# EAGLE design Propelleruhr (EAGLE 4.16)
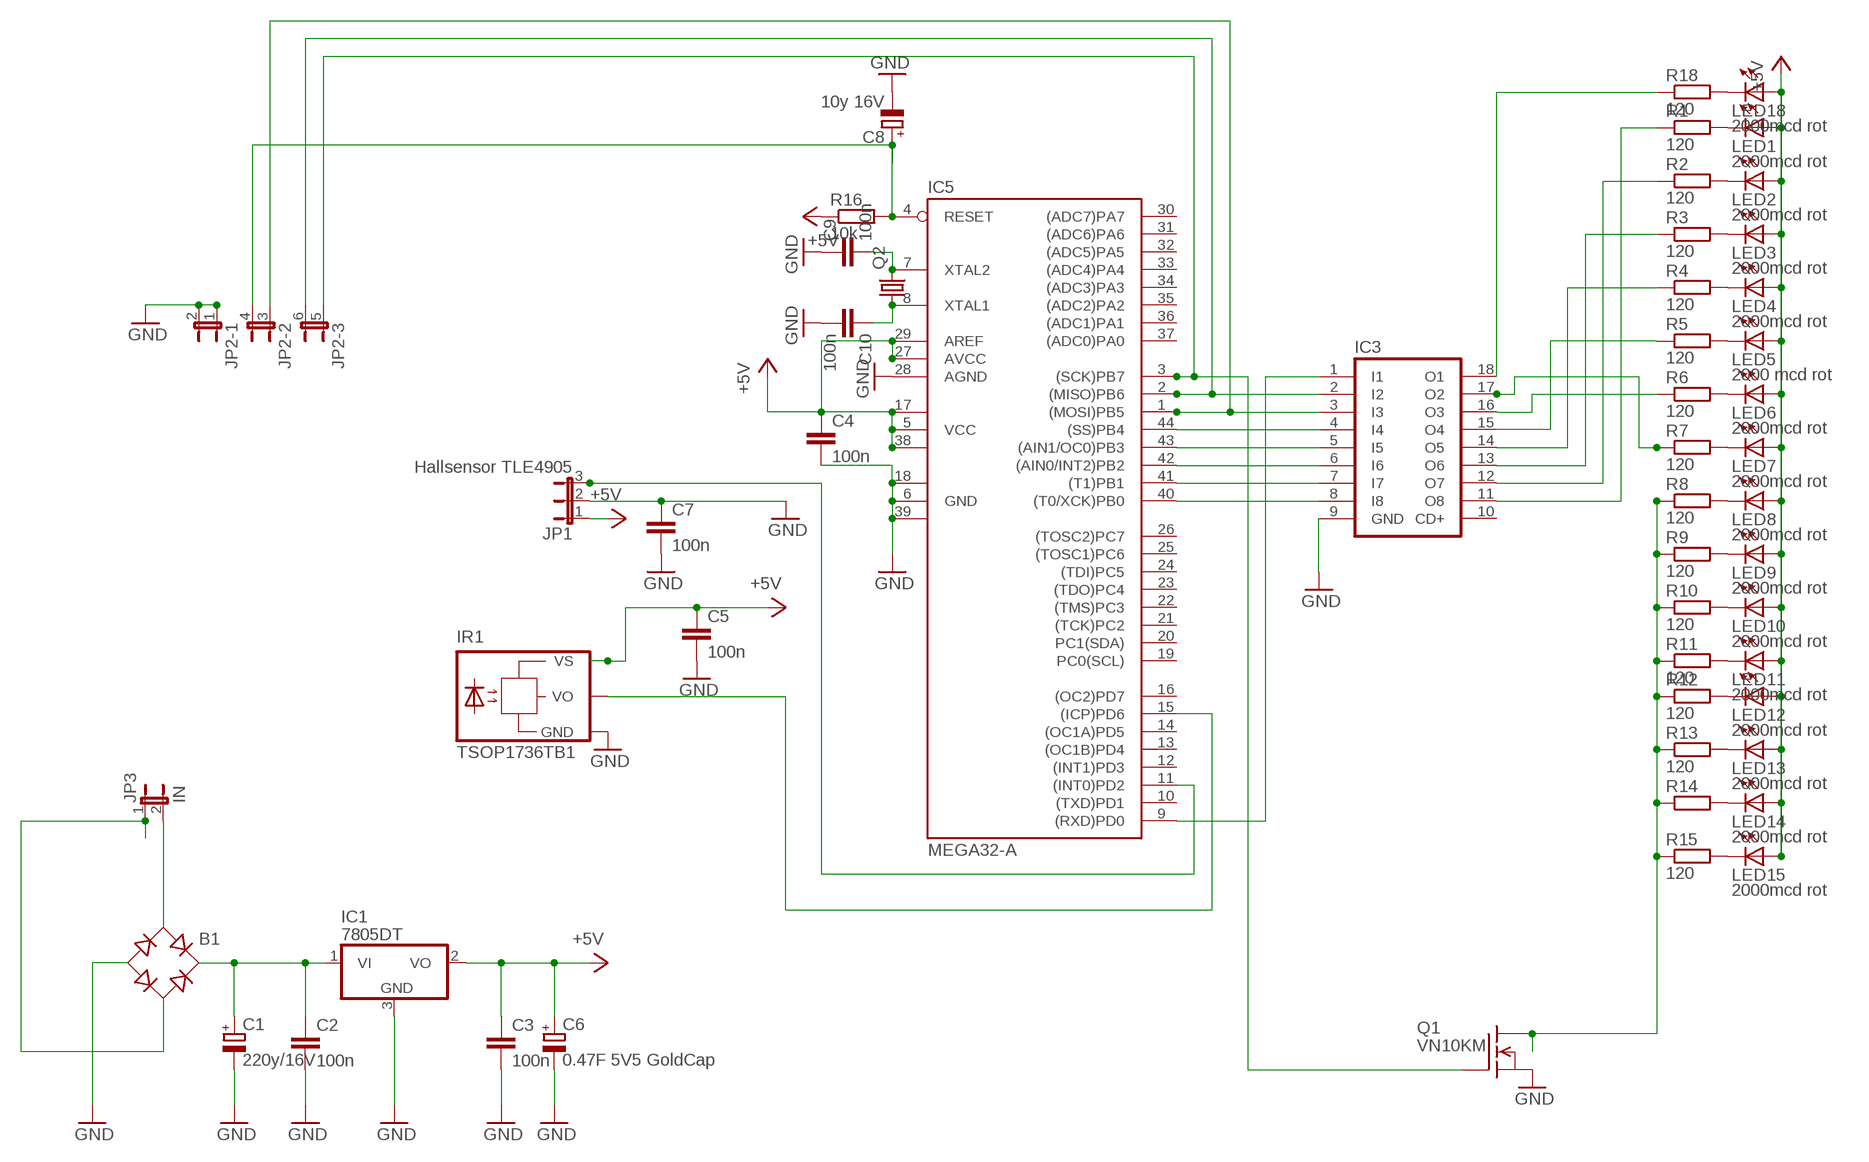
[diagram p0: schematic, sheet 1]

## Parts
B1  RB1A  [RB1A]
C1  220y/16V  CPOL-EU140CLH-0810  [140CLH-0810]
C2  100n  C-EUC1812  [C1812]
C3  100n  C-EUC1812  [C1812]
C4  100n  C-EUC1812  [C1812]
C5  100n  C-EUC1812  [C1812]
C6  0.47F 5V5 GoldCap  CPOL-EU140CLH-0810  [140CLH-0810]
C7  100n  C-EUC1812  [C1812]
C8  10y 16V  CPOL-EU140CLH-0810  [140CLH-0810]
C9  100n  C-EUC1812  [C1812]
C10  100n  C-EUC1812  [C1812]
IC1  7805DT  [TO252]
IC3  ULN2803A  [DIL18]
IC5  MEGA32-A  [TQFP44]
IR1  TSOP1736TB1  [TSOP17_TB1]
JP1  Hallsensor TLE4905  JP2W  [JP2W]
JP2  JP3QE  [JP3Q]
JP3  IN  JP1E  [JP1]
LED1  2000mcd rot  LED3MM  [LED3MM]
LED2  2000mcd rot  LED3MM  [LED3MM]
LED3  2000mcd rot  LED3MM  [LED3MM]
LED4  2000mcd rot  LED3MM  [LED3MM]
LED5  2000 mcd rot  LED3MM  [LED3MM]
LED6  2000mcd rot  LED3MM  [LED3MM]
LED7  2000mcd rot  LED3MM  [LED3MM]
LED8  2000mcd rot  LED3MM  [LED3MM]
LED9  2000mcd rot  LED3MM  [LED3MM]
LED10  2000mcd rot  LED3MM  [LED3MM]
LED11  2000mcd rot  LED3MM  [LED3MM]
LED12  2000mcd rot  LED3MM  [LED3MM]
LED13  2000mcd rot  LED3MM  [LED3MM]
LED14  2000mcd rot  LED3MM  [LED3MM]
LED15  2000mcd rot  LED3MM  [LED3MM]
LED18  2000mcd rot  LED3MM  [LED3MM]
Q1  VN10KM  [TO237]
Q2  CRYSTALHC18U-V  [HC18U-V]
R1  120  R-EU_M0805  [M0805]
R2  120  R-EU_M0805  [M0805]
R3  120  R-EU_M0805  [M0805]
R4  120  R-EU_M0805  [M0805]
R5  120  R-EU_M0805  [M0805]
R6  120  R-EU_M0805  [M0805]
R7  120  R-EU_M0805  [M0805]
R8  120  R-EU_M0805  [M0805]
R9  120  R-EU_M0805  [M0805]
R10  120  R-EU_M0805  [M0805]
R11  120  R-EU_M0805  [M0805]
R12  120  R-EU_M0805  [M0805]
R13  120  R-EU_M0805  [M0805]
R14  R-EU_M0805  [M0805]
R15  120  R-EU_M0805  [M0805]
R16  10k  R-R0805  [R0805]
R18  120  R-EU_M0805  [M0805]

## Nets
+5V: C3.1 C4.1 C5.1 C6.+ IC1.2(VO) IC5.5(VCC) IC5.17(VCC1) IC5.27(AVCC) IC5.29(AREF) IC5.38(VCC2) IR1.VS JP1.1 LED1.A LED2.A LED3.A LED4.A LED5.A LED6.A LED7.A LED8.A LED9.A LED10.A LED11.A LED12.A LED13.A LED14.A LED15.A LED18.A R16.1
GND: B1.- C1.- C2.2 C3.2 C4.2 C5.2 C6.- C7.1 C7.2 C8.- C9.1 C10.2 IC1.3(GND) IC3.9(GND) IC5.6(GND) IC5.18(GND1) IC5.28(AGND) IC5.39(GND2) IR1.GND JP1.2 JP2.1 JP2.2 Q1.3(S)
N$1: C8.+ IC5.4(RESET) JP2.4 R16.2
N$2: IC3.8(I8) IC5.40((T0/XCK)PB0)
N$3: IC3.7(I7) IC5.41((T1)PB1)
N$4: IC3.6(I6) IC5.42((AIN0/INT2)PB2)
N$5: IC3.5(I5) IC5.43((AIN1/OC0)PB3)
N$6: IC3.4(I4) IC5.44((SS)PB4)
N$7: IC3.3(I3) IC5.1((MOSI)PB5) JP2.3
N$8: IC3.2(I2) IC5.2((MISO)PB6) JP2.6
N$9: IC3.1(I1) IC5.9((RXD)PD0)
N$10: IC5.3((SCK)PB7) JP2.5 Q1.2(G)
N$11: IC5.15((ICP)PD6) IR1.VO
N$12: IC5.11((INT0)PD2) JP1.3
N$13: LED1.K(C) R1.2
N$14: LED2.K(C) R2.2
N$15: LED3.K(C) R3.2
N$16: LED4.K(C) R4.2
N$17: LED5.K(C) R5.2
N$18: LED6.K(C) R6.2
N$19: LED7.K(C) R7.2
N$20: LED8.K(C) R8.2
N$21: LED9.K(C) R9.2
N$22: LED10.K(C) R10.2
N$23: LED11.K(C) R11.2
N$24: LED12.K(C) R12.2
N$25: LED13.K(C) R13.2
N$26: LED14.K(C) R14.2
N$27: LED15.K(C) R15.2
N$28: C9.2 IC5.7(XTAL2) Q2.2
N$29: C10.1 IC5.8(XTAL1) Q2.1
N$30: LED18.K(C) R18.2
N$31: Q1.1(D) R8.1 R9.1 R10.1 R11.1 R12.1 R13.1 R14.1 R15.1
N$32: IC3.16(O3) R6.1
N$33: IC3.11(O8) R1.1
N$34: IC3.17(O2) R7.1
N$35: IC3.12(O7) R2.1
N$36: IC3.13(O6) R3.1
N$37: IC3.14(O5) R4.1
N$38: IC3.15(O4) R5.1
N$39: IC3.18(O1) R18.1
N$42: B1.+ C1.+ C2.1 IC1.1(VI)
N$43: B1.AC1 JP3.2
N$44: B1.AC2 JP3.1
Unconnected: IC3.10(CD+) IC5.10((TXD)PD1) IC5.12((INT1)PD3) IC5.13((OC1B)PD4) IC5.14((OC1A)PD5) IC5.16((OC2)PD7) IC5.19(PC0(SCL)) IC5.20(PC1(SDA)) IC5.21((TCK)PC2) IC5.22((TMS)PC3) IC5.23((TDO)PC4) IC5.24((TDI)PC5) IC5.25((TOSC1)PC6) IC5.26((TOSC2)PC7) IC5.30((ADC7)PA7) IC5.31((ADC6)PA6) IC5.32((ADC5)PA5) IC5.33((ADC4)PA4) IC5.34((ADC3)PA3) IC5.35((ADC2)PA2) IC5.36((ADC1)PA1) IC5.37((ADC0)PA0)

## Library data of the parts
B1 = rectifier:RB1A: RECTIFIER 1 A
C1 C6 C8 = rcl:CPOL-EU: POLARIZED CAPACITOR, European symbol
C2-C5 C7 C9 C10 = rcl:C-EU: CAPACITOR, European symbol
IC1 = linear:78*: Positive VOLTAGE REGULATOR Source: http://cache.national.com/ds/LM/LM78L05.pdf http://www.fairchildsemi.com/ds/LM/LM7805.pdf
IC3 = uln-udn:ULN2803A: DRIVER ARRAY
IC5 = atmel:MEGA32: MICROCONTROLLER 32 Kbytes FLASH 2 Kbytes SRAM 1 Kbytes EEPROM USART 8-channel 10 bit ADC Source: www.atmel.com .. doc2503.pdf
IR1 = telefunken:TSOP17*TB1: TSOP17..TB1 IR Receiver Modules for Remote Control Systems Source: http://www.vishay.com/docs/82042/82042.pdf
JP1 = jumper:JP2W: JUMPER
JP2 = jumper:JP3QE: JUMPER
JP3 = jumper:JP1E: JUMPER
LED1-LED15 LED18 = led:LED: LED
Q1 = transistor-fet:VN10KM: N-Channel Enhancement MOSFET (VMOS); 60V; 0,5A; 5,0Ohm
Q2 = crystal:CRYSTAL: CRYSTAL
R1-R15 R18 = rcl:R-EU_: RESISTOR, European symbol
R16 = quantum-sensor:R: Resistor

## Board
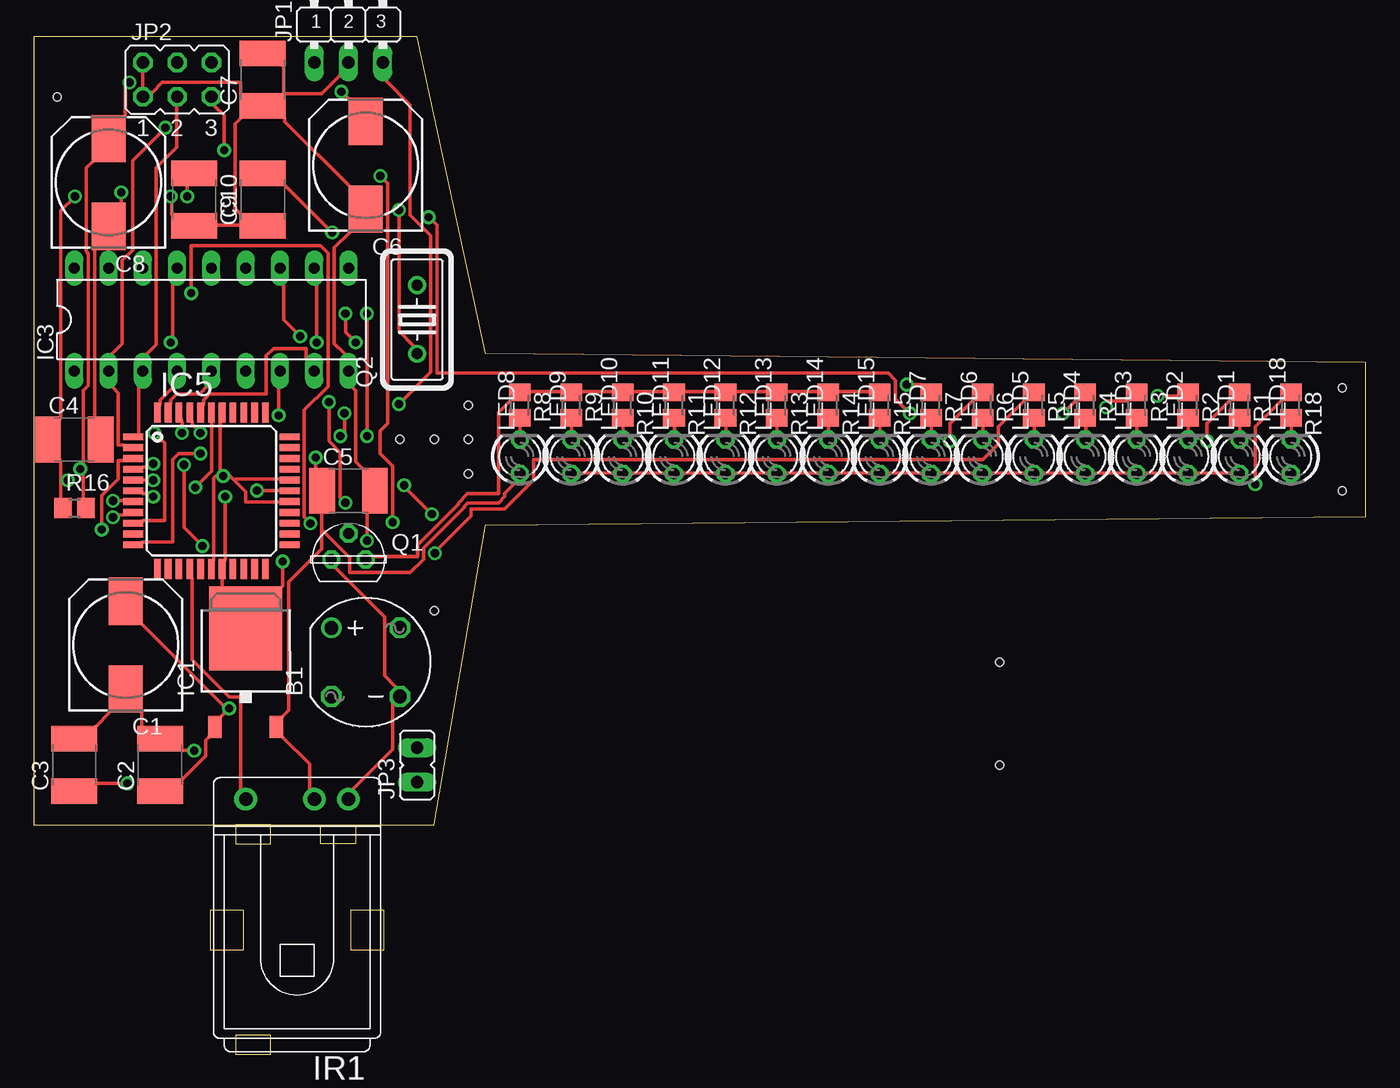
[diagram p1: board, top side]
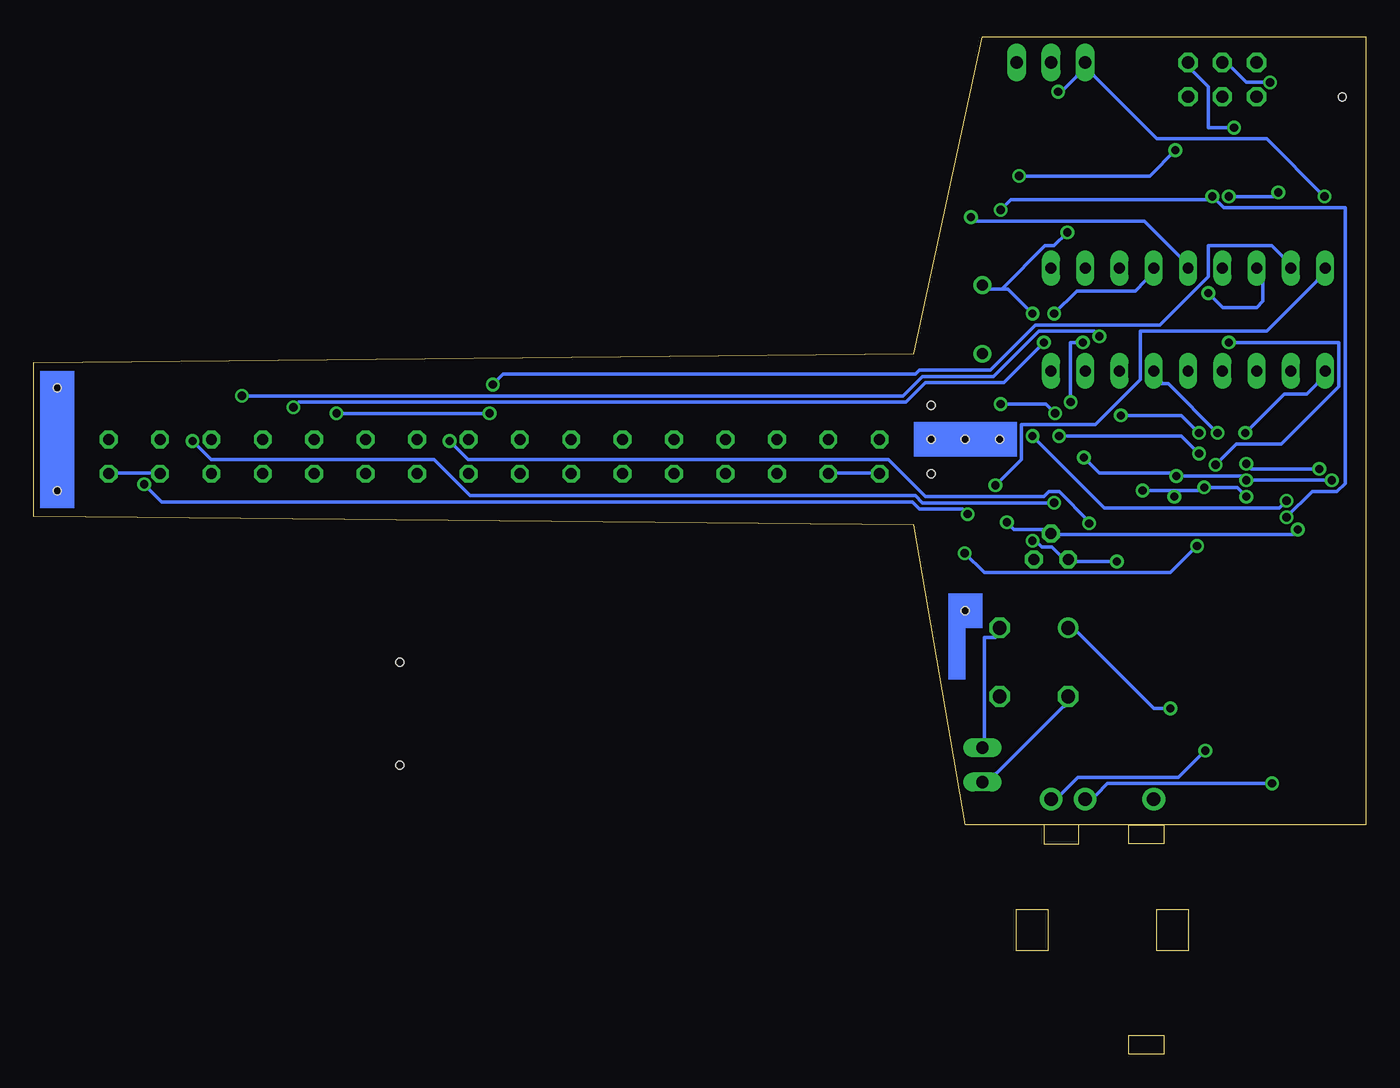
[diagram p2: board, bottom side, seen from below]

Size 98.73 x 75.41 mm. Coordinates in mm from the lower left corner, seen from the top.
Outline: 0,17 29.68,17 33.49,39.22 98.73,39.86 98.73,51.28 33.49,51.92 28.41,75.41 0,75.41 0,17
Copper layers (1*16): Top 0.035mm / dielectric 1.5mm / Bottom 0.035mm
Design rules "default": minimum track width 10mil, minimum drill 24mil, track to track 8mil, track to pad 8mil, pad to pad 8mil, via to via 8mil, smd to smd 8mil, copper to edge 40mil, drill to drill 8mil, minimum pad ring 10mil, minimum via ring 8mil, stop-mask expansion 4mil, vias tented up to drill 0mil, thermal gap 10mil
Holes 0.6 mm at 27.14,45.57 29.68,45.57 32.22,45.57 1.74,70.97 29.68,32.87 71.59,29.06 71.59,21.44 32.22,48.11 32.22,43.03 96.99,49.38 96.99,41.76

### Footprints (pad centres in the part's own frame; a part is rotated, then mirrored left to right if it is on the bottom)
RB1A = drill 1.016 round: + -2.54,2.54 | drill 1.016 octagon: - 2.54,-2.54; AC1 2.54,2.54; AC2 -2.54,-2.54
140CLH-0810 = smd 3.5 x 2.5: + 3.25,0; - -3.25,0
C1812 = smd 1.9 x 3.4: 1 -1.95,0; 2 1.95,0
TO252 = smd 1 x 1.6: 1 -2.28,-4.8; 2 2.28,-4.8 | smd 5.4 x 6.2: 3 0,2.5
DIL18 = drill 0.813 long: 1 -10.16,-3.81; 2 -7.62,-3.81; 3 -5.08,-3.81; 4 -2.54,-3.81; 5 0,-3.81; 6 2.54,-3.81; 7 5.08,-3.81; 8 7.62,-3.81; 9 10.16,-3.81; 10 10.16,3.81; 11 7.62,3.81; 12 5.08,3.81; 13 2.54,3.81; 14 0,3.81; 15 -2.54,3.81; 16 -5.08,3.81; 17 -7.62,3.81; 18 -10.16,3.81
TQFP44 = smd 1.5 x 0.5: 1 -5.8,4; 2 -5.8,3.2; 3 -5.8,2.4; 4 -5.8,1.6; 5 -5.8,0.8; 6 -5.8,0; 7 -5.8,-0.8; 8 -5.8,-1.6; 9 -5.8,-2.4; 10 -5.8,-3.2; 11 -5.8,-4; 23 5.8,-4; 24 5.8,-3.2; 25 5.8,-2.4; 26 5.8,-1.6; 27 5.8,-0.8; 28 5.8,0; 29 5.8,0.8; 30 5.8,1.6; 31 5.8,2.4; 32 5.8,3.2; 33 5.8,4 | smd 0.5 x 1.5: 12 -4,-5.8; 13 -3.2,-5.8; 14 -2.4,-5.8; 15 -1.6,-5.8; 16 -0.8,-5.8; 17 0,-5.8; 18 0.8,-5.8; 19 1.6,-5.8; 20 2.4,-5.8; 21 3.2,-5.8; 22 4,-5.8; 34 4,5.8; 35 3.2,5.8; 36 2.4,5.8; 37 1.6,5.8; 38 0.8,5.8; 39 0,5.8; 40 -0.8,5.8; 41 -1.6,5.8; 42 -2.4,5.8; 43 -3.2,5.8; 44 -4,5.8
TSOP17_TB1 = drill 1 pad 1.676 round: GND 0,-3.81; VO 0,3.81; VS 0,-1.27
JP2W = drill 0.914 long: 1 -2.54,-1.27; 2 0,-1.27; 3 2.54,-1.27
JP3Q = drill 0.914 octagon: 1 -2.54,-1.27; 2 -2.54,1.27; 3 0,-1.27; 4 0,1.27; 5 2.54,-1.27; 6 2.54,1.27
JP1 = drill 0.914 long: 1 0,-1.27; 2 0,1.27
LED3MM = drill 0.813 octagon: A -1.27,0; K 1.27,0
TO237 = drill 0.813 octagon: 1 1.27,0; 2 0,1.905; 3 -1.27,0
HC18U-V = drill 0.813 round: 1 -2.54,0; 2 2.54,0
M0805 = smd 1.3 x 1.6: 1 -0.95,0; 2 0.95,0
R0805 = smd 1.3 x 1.5: 1 -0.85,0; 2 0.85,0

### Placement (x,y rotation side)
B1  24.6,29.06 0 top
C1  6.82,30.33 90 top
C2  9.36,21.44 90 top
C3  3.01,21.44 90 top
C4  3.01,45.57 0 top
C5  23.33,41.76 0 top
C6  24.6,65.89 90 top
C7  16.98,72.24 90 top
C8  5.55,64.62 90 top
C9  16.98,63.35 90 top
C10  11.9,63.35 270 top
IC1  15.71,29.06 0 top
IC3  13.17,54.46 0 top
IC5  13.17,41.76 0 top
IR1  19.52,18.9 90 top
JP1  23.33,74.78 0 top
JP2  10.63,72.24 0 top
JP3  28.41,21.44 0 top
LED1  89.37,44.3 90 top
LED2  85.56,44.3 90 top
LED3  81.75,44.3 90 top
LED4  77.94,44.3 90 top
LED5  74.13,44.3 90 top
LED6  70.32,44.3 90 top
LED7  66.51,44.3 90 top
LED8  36.03,44.3 90 top
LED9  39.84,44.3 90 top
LED10  43.65,44.3 90 top
LED11  47.46,44.3 90 top
LED12  51.27,44.3 90 top
LED13  55.08,44.3 90 top
LED14  58.89,44.3 90 top
LED15  62.7,44.3 90 top
LED18  93.18,44.3 90 top
Q1  23.33,36.68 0 top
Q2  28.41,54.46 90 top
R1  89.37,48.11 270 top
R2  85.56,48.11 270 top
R3  81.75,48.11 270 top
R4  77.94,48.11 270 top
R5  74.13,48.11 270 top
R6  70.32,48.11 270 top
R7  66.51,48.11 270 top
R8  36.03,48.11 270 top
R9  39.84,48.11 270 top
R10  43.65,48.11 270 top
R11  47.46,48.11 270 top
R12  51.27,48.11 270 top
R13  55.08,48.11 270 top
R14  58.89,48.11 270 top
R15  62.7,48.11 270 top
R16  3.01,40.49 0 top
R18  93.18,48.11 270 top

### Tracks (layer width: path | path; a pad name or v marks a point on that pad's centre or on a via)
+5V  (via drill 0.61)
  Top 0.254: LED9.A 40.48,43.08 43.07,43.08 LED10.A 44.28,43.08 46.88,43.08 LED11.A 48.09,43.08 50.69,43.08 LED12.A 51.91,43.08 54.5,43.08 LED13.A 55.71,43.08 58.31,43.08 LED14.A 59.52,43.08 62.12,43.08 LED15.A 63.34,43.08 65.93,43.08 LED7.A 67.14,43.08 69.74,43.08 LED6.A 70.95,43.08 73.55,43.08 LED5.A 74.77,43.08 77.36,43.08 LED4.A 78.58,43.08 81.17,43.08 LED3.A 82.39,43.08 84.98,43.08 LED2.A 86.19,43.08 88.79,43.08 LED1.A | IR1.VS 20.43,19.69 20.43,21.52 18.45,23.5 IC1.2 18.45,25.02 18.91,25.48 18.91,35 21.35,37.44 21.35,38.81 | v6.95,20.07 4.66,20.07 C3.1 | 21.35,38.81 21.35,40.11 C5.1 20.89,43.39 v20.89,44.22 | v22.8,71.35 23.41,70.74 C6.+ | 1.99,42.55 1.99,43.92 C4.1 1.99,47.2 1.99,62.51 v3.06,63.58 | 1.99,42.55 1.99,41.18 R16.1 | 13.81,43.16 13.35,42.7 13.35,36.68 IC5.17 | 13.81,43.16 13.81,46.81 IC5.38 | v8.85,42.55 8.09,42.55 IC5.5 | 13.81,43.16 13.88,43.08 13.88,43 v14.03,42.85 14.49,42.93 14.87,42.55 | 14.87,42.55 15.71,41.71 15.71,40.95 18.22,40.95 IC5.27 | IC5.29 18.22,42.62 14.95,42.62 14.87,42.55 | v2.53,42.55 1.99,42.55 | LED8.A 35.75,42.39 34.91,41.56 34.91,41.33 34.45,40.87 32.17,40.87 31.94,40.64 31.94,40.57 28.89,37.52 28.89,36.68 27.9,35.69 23.41,35.69 23.41,36.83 21.42,38.81 21.35,38.81
  Bottom 0.254: LED1.A 90,43.08 92.6,43.08 LED18.A | LED8.A 36.66,43.08 39.26,43.08 LED9.A | v6.95,20.07 19.14,20.07 19.98,19.23 IR1.VS | v22.8,71.35 22.57,71.35 21.42,72.49 JP1.1 20.13,72.49 15.48,67.85 7.33,67.85 v3.06,63.58 | v2.53,42.55 v8.85,42.55 9.16,42.85 v14.03,42.85 14.49,43.08 19.75,43.08 v20.89,44.22
GND  (via drill 0.61)
  Top 0.254: v8.85,41.33 8.85,41.56 8.09,41.56 IC5.6 | v11.98,42.01 13.2,43.23 13.2,46.81 IC5.39 | v16.55,41.78 18.22,41.78 IC5.28 | C3.2 4.66,24.34 5.58,25.25 5.58,25.4 C1.- 8.01,25.4 8.01,24.34 C2.2 10.99,22.51 v11.9,22.51 | Q1.3 22.34,36.07 26,32.41 26,28.07 26.83,27.23 B1.- 26.61,26.01 26.61,22.58 23.71,19.69 IR1.GND | v18.45,36.53 18.45,34.7 18.38,34.62 IC1.3 13.96,34.62 13.96,35.23 IC5.18 14.19,36.68 v14.19,41.33 | C4.2 4.51,47.2 4.51,59.69 C8.- 6.49,63.05 v6.49,63.88 | JP2.2 JP2.1 8.78,71.28 9.54,72.04 15.33,72.04 15.33,71.2 C7.1 | 18.61,71.2 21.35,71.2 22.64,72.49 JP1.2 | C7.1 18.61,71.2 | C7.2 18.53,73.26 18.53,71.28 18.61,71.2 | C7.1 18.61,69.37 18.61,69.14 23.41,64.34 C6.- 23.41,60.91 22.26,59.77 22.26,52.68 23.02,51.92 IC3.9 23.63,49.41 23.86,49.18 23.86,43.92 24.4,43.39 C5.2 24.7,40.11 v24.7,38.05 | C7.1 15.33,69.37 14.95,68.99 14.95,62.66 15.33,62.28 C9.1 15.33,61.44 13.58,61.44 C10.2 10.22,62.28 10.22,63.5 v10.15,63.58
  Bottom 0.254: v8.85,41.33 9.54,42.01 v11.98,42.01 12.43,41.78 14.19,41.78 | 14.19,41.78 v16.55,41.78 | v18.45,36.53 21.42,36.53 Q1.3 22.64,36.98 23.25,37.59 24.02,37.59 24.47,38.05 v24.7,38.05 | v11.9,22.51 13.88,20.53 21.35,20.53 22.57,19.31 IR1.GND | v14.19,41.33 14.19,41.78 | v6.49,63.88 6.79,63.58 v10.15,63.58
N$1  (via drill 0.61)
  Top 0.254: 3.67,43.39 3.67,49.18 4.05,49.56 4.05,59.39 3.97,59.39 3.97,59.46 3.9,59.54 3.9,65.71 4.36,66.17 C8.+ 6.79,69.6 6.79,71.73 v7.1,72.04 | 3.67,43.39 3.67,41.18 R16.2 | v8.85,43.77 8.85,43.54 8.09,43.54 IC5.4 | 3.67,43.39 v3.44,43.39
  Bottom 0.254: v8.85,43.77 8.47,43.39 v3.44,43.39 | v7.1,72.04 8.85,72.04 10,73.18 JP2.4
N$2
  Top 0.254: IC5.40 12.59,48.26 12.59,48.49 13.04,48.95 17.23,48.95 17.23,51.77 17.77,52.3 20.21,52.3 20.21,51.61 IC3.8
N$3  (via drill 0.61)
  Top 0.254: v12.36,46.05 11.75,46.66 11.75,46.81 IC5.41 | v18.15,47.35 18.15,49.41 IC3.7
  Bottom 0.254: v12.36,46.05 13.65,47.35 v18.15,47.35
N$4  (via drill 0.61)
  Top 0.254: v10.99,46.05 10.99,46.81 IC5.42
  Bottom 0.254: v10.99,46.05 14.64,49.71 15.1,49.71 IC3.6
N$5
  Top 0.254: IC5.43 10.15,48.26 10.15,48.49 10.61,48.95 12.36,48.95 12.36,49.02 12.81,49.48 IC3.5
N$6
  Top 0.254: IC5.44 9.38,48.26 9.38,48.49 10.3,49.41 IC3.4
N$7
  Top 0.254: IC5.1 7.79,45.98 7.79,49.41 IC3.3 8.39,51.92 9.08,52.61 9.08,65.71 10.61,67.24 10.61,70.28 JP2.3
N$8  (via drill 0.61)
  Top 0.254: IC5.2 6.64,45.14 6.26,45.14 6.26,49.02 5.88,49.41 IC3.2 5.8,51.92 6.57,52.68 6.57,58.85 7.33,59.62 7.33,66.25 v9.77,68.68
  Bottom 0.254: v9.77,68.68 11.67,68.68 11.67,71.73 12.81,72.88 JP2.6
N$9  (via drill 0.61)
  Top 0.254: v8.93,46.05 9.69,45.29 9.69,39.58 8.09,39.58 IC5.9
  Bottom 0.254: v8.93,46.05 6.03,48.95 4.36,48.95 3.59,49.71 IC3.1
N$10  (via drill 0.61)
  Top 0.254: v5.04,38.89 5.04,41.4 6.26,42.62 6.26,44 6.64,44 IC5.3 | v14.11,67.01 14.11,69.6 13.42,70.28 JP2.5 | v25.69,65.1 26.23,64.57 26.23,46.74 25.69,46.2 25.69,44.53 26.61,43.61 v26.61,39.42
  Bottom 0.254: v5.04,38.89 5.42,38.51 22.72,38.51 Q1.2 23.94,38.89 26.07,38.89 v26.61,39.42 | v14.11,67.01 16.02,65.1 v25.69,65.1
N$11
  Top 0.254: IC5.15 11.75,35.23 11.75,29.21 14.49,26.47 15.33,26.47 15.33,19.69 IR1.VO
N$12  (via drill 0.61)
  Top 0.254: v12.36,44.53 10.76,44.53 10.3,44.07 10.3,37.97 8.09,37.97 IC5.11 | v22.72,45.82 23.02,46.13 v23.02,47.5 | v27.06,48.19 29.43,50.55 29.43,60.68 27.9,62.21 27.9,70.36 26.15,72.11 JP1.3
  Bottom 0.254: v12.36,44.53 13.65,45.82 v22.72,45.82 | v23.02,47.5 23.71,48.19 v27.06,48.19
N$13
  Top 0.254: R1.2 89.39,46.59 89.39,46.2 LED1.K
N$14
  Top 0.254: R2.2 85.58,46.59 85.58,46.2 LED2.K
N$15
  Top 0.254: R3.2 81.78,46.59 81.78,46.2 LED3.K
N$16
  Top 0.254: R4.2 77.97,46.59 77.97,46.2 LED4.K
N$17
  Top 0.254: R5.2 74.16,46.59 74.16,46.2 LED5.K
N$18
  Top 0.254: R6.2 70.34,46.59 70.34,46.2 LED6.K
N$19
  Top 0.254: R7.2 66.53,46.59 66.53,46.2 LED7.K
N$20
  Top 0.254: R8.2 36.05,46.59 36.05,46.2 LED8.K
N$21
  Top 0.254: R9.2 39.87,46.59 39.87,46.2 LED9.K
N$22
  Top 0.254: R10.2 43.67,46.59 43.67,46.2 LED10.K
N$23
  Top 0.254: R11.2 47.48,46.59 47.48,46.2 LED11.K
N$24
  Top 0.254: R12.2 51.3,46.59 51.3,46.2 LED12.K
N$25
  Top 0.254: R13.2 55.1,46.59 55.1,46.2 LED13.K
N$26
  Top 0.254: R14.2 58.91,46.59 58.91,46.2 LED14.K
N$27
  Top 0.254: R15.2 62.73,46.59 62.73,46.2 LED15.K
N$28  (via drill 0.61)
  Top 0.254: v5.88,41.02 6.64,41.02 IC5.7 | v24.7,45.82 v24.7,54.89 | v22.11,60.91 18.61,64.42 C9.2
  Bottom 0.254: v5.88,41.02 6.41,40.49 19.37,40.49 v24.7,45.82 | v24.7,54.89 26.53,56.72 26.91,56.72 | 26.91,56.72 27.83,56.72 Q2.2 | v22.11,60.91 23.1,59.92 23.79,59.92 26.91,56.8 26.91,56.72
N$29  (via drill 0.61)
  Top 0.254: v5.88,39.8 5.88,39.96 6.64,39.96 IC5.8 | v11.37,63.58 11.37,64.42 C10.1 | v27.06,62.59 27.06,53.6 28.13,52.53 Q2.1
  Bottom 0.254: v5.88,39.8 3.97,41.71 2.15,41.71 1.54,42.32 1.54,62.74 10.53,62.74 v11.37,63.58 11.82,63.35 26.3,63.35 v27.06,62.59
N$30
  Top 0.254: R18.2 93.2,46.59 93.2,46.2 LED18.K
N$31
  Top 0.254: R15.1 61.96,49.1 59.68,49.1 R14.1 58.15,49.1 55.87,49.1 R13.1 54.34,49.1 52.06,49.1 R12.1 50.53,49.1 48.25,49.1 R11.1 46.72,49.1 44.44,49.1 R10.1 42.91,49.1 40.63,49.1 R9.1 39.1,49.1 36.82,49.1 R8.1 35.29,48.42 34.45,47.58 34.45,41.56 32.17,41.56 31.48,40.87 31.48,40.8 28.43,37.75 28.43,36.91 25.23,36.91 Q1.1
N$32  (via drill 0.61)
  Top 0.254: v67.91,45.44 67.91,46.74 69.58,48.42 R6.1 | v20.51,39.35 20.05,39.8 20.05,47.73 21.81,49.48 21.81,59.39 21.27,59.92 11.67,59.92 v11.67,56.42
  Bottom 0.254: v67.91,45.44 66.53,44.07 35.37,44.07 32.63,41.33 23.86,41.33 23.48,41.71 22.72,41.71 20.51,39.5 v20.51,39.35 | v11.67,56.42 10.61,55.35 8.09,55.35 7.63,55.81 7.63,57.18 IC3.16
N$33  (via drill 0.61)
  Top 0.254: v86.96,45.44 86.96,46.74 88.63,48.42 R1.1 | v23.1,40.87 22.72,41.25 22.72,44.61 21.88,45.44 v21.88,48.34 | v20.97,52.76 20.97,57.03 IC3.11
  Bottom 0.254: v86.96,45.44 85.58,44.07 69.05,44.07 66.38,41.4 33.39,41.4 32.85,40.87 v23.1,40.87 | v21.88,48.34 21.88,52.76 v20.97,52.76
N$34  (via drill 0.61)
  Top 0.254: v64.71,49.63 65.77,49.63 R7.1
  Bottom 0.254: v64.71,49.63 63.95,50.4 33.39,50.4 33.08,50.7 27.83,50.7 24.47,54.05 15.25,54.05 11.67,57.64 11.67,59.92 6.95,59.92 6.18,59.16 IC3.17
N$35  (via drill 0.61)
  Top 0.254: v83.3,48.8 84.82,48.8 R2.1 | v19.75,53.22 18.53,54.44 18.53,57.03 IC3.12
  Bottom 0.254: v83.3,48.8 34.3,48.8 32.85,50.24 27.6,50.24 24.24,53.6 20.13,53.6 v19.75,53.22
N$36  (via drill 0.61)
  Top 0.254: v79.49,47.96 79.49,48.42 81.01,48.42 R3.1 | v23.86,52.76 23.1,53.52 v23.1,54.89
  Bottom 0.254: v79.49,47.96 79.11,48.34 34.07,48.34 32.63,49.79 26.83,49.79 v23.86,52.76 | v23.1,54.89 21.42,56.57 17.08,56.57 16.32,57.33 IC3.13
N$37  (via drill 0.61)
  Top 0.254: v76.29,47.5 77.2,48.42 R4.1 | v64.94,47.5 63.87,48.57 63.87,49.94 63.34,50.47 29.88,50.47 29.88,61.44 v29.27,62.05
  Bottom 0.254: v64.94,47.5 v76.29,47.5 | v29.27,62.05 28.97,61.75 16.4,61.75 13.81,59.16 IC3.14
N$38  (via drill 0.61)
  Top 0.254: v29.73,37.14 29.73,37.21 32.4,39.88 32.4,40.41 34.91,40.41 37.05,42.55 37.05,44.07 70.34,44.07 71.49,45.21 71.49,46.51 73.39,48.42 R5.1 | v12.51,37.67 11.14,39.04 v11.14,43.69 | v10.15,52.76 10.3,52.91 10.3,57.03 IC3.15
  Bottom 0.254: v29.73,37.14 28.28,35.69 14.49,35.69 v12.51,37.67 | v11.14,43.69 9.61,45.21 6.26,45.21 1.99,49.48 1.99,52.76 v10.15,52.76
N$39  (via drill 0.61)
  Top 0.254: v90.54,42.24 90.54,46.51 92.44,48.42 R18.1 | v29.5,40.03 27.45,42.09 v27.45,42.17
  Bottom 0.254: v90.54,42.24 89.24,40.95 33.62,40.95 33.08,40.41 29.88,40.41 v29.5,40.03 | v27.45,42.17 25.54,44.07 25.54,46.66 20.05,46.66 16.7,50.02 16.7,53.6 7.33,53.6 3.59,57.33 IC3.18
N$42  (via drill 0.61)
  Top 0.254: C2.1 10.99,20.37 12.74,22.13 12.74,23.27 12.97,23.5 IC1.1 13.88,25.02 v14.49,25.63 14.03,25.86 8.01,31.88 C1.+
  Bottom 0.254: v14.49,25.63 15.71,25.63 21.35,31.27 B1.+
N$43
  Bottom 0.254: JP3.2 28.28,23.34 28.28,30.89 27.45,30.89 B1.AC1
N$44
  Bottom 0.254: JP3.1 27.37,20.83 22.42,25.78 22.34,25.78 B1.AC2
(copper drawn outside any net)
  shapes: Bottom area x5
